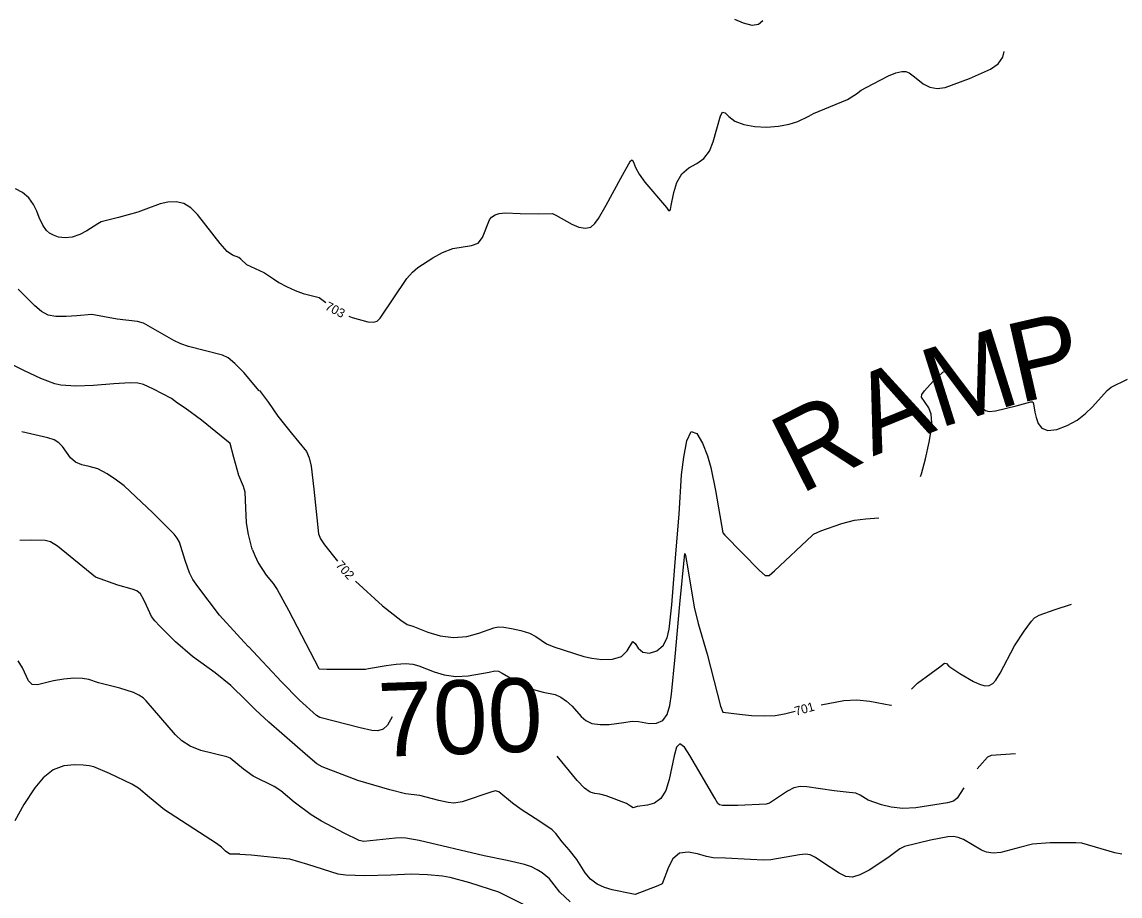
# Model space of a CAD drawing. Extents: x -291892836 to 2945206, y -477993085 to 1832792.
# Drawn here: x 1850526.8 to 1851017.9, y 544137.8 to 544528.7 of the extents above; entities that cross this region are included whole.
import ezdxf

# ---------------------------------------------------------------- set-up
doc = ezdxf.new("R2010")
doc.units = 0
for name, color, linetype in [('DT_X_Contour_Minor', 7, 'Continuous'), ('DT_X_Terrain_Ground_Line', 7, 'Continuous'), ('Level 19', 7, 'Continuous'), ('Level 40', 7, 'Continuous')]:
    doc.layers.add(name, color=color, linetype=linetype)

msp = doc.modelspace()

# ---------------------------------------------------------------- linework, layer by layer
at = {"layer": 'DT_X_Contour_Minor'}
for points in [[(1850858.2, 544529.18), (1850856.23, 544527.62), (1850853.41, 544527.18), (1850849.6, 544528.12), (1850845.59, 544529.87)], [(1850673.08, 544397.16), (1850674.59, 544396.56), (1850681.6, 544394.53), (1850683.91, 544394.4), (1850685.65, 544394.96), (1850687.06, 544396.28), (1850699.04, 544413.96), (1850701.49, 544416.74), (1850703.86, 544418.83), (1850710.55, 544423.28), (1850714.99, 544425.67), (1850719.61, 544427.42), (1850727.86, 544428.69), (1850730.87, 544429.83), (1850732.86, 544432.27), (1850735.9, 544440.23), (1850736.79, 544441.36), (1850738.49, 544442.45), (1850740.22, 544443.02), (1850743.02, 544443.31), (1850749.6, 544443.09), (1850757.91, 544442.82), (1850764.05, 544442.99), (1850765.59, 544442.32), (1850772.75, 544438.2), (1850775.95, 544436.94), (1850778.89, 544436.42), (1850781.21, 544436.98), (1850783.06, 544438.52), (1850784.7, 544440.81), (1850788.07, 544446.84), (1850794.67, 544458.87), (1850798.93, 544466.58), (1850799.68, 544467), (1850800.32, 544465.95), (1850801.21, 544463.68), (1850802.82, 544460.58), (1850805.42, 544457.09), (1850815.08, 544445.74), (1850816.03, 544444.45), (1850816.59, 544444.45), (1850816.95, 544444.81), (1850817.24, 544446.56), (1850818.4, 544452.47), (1850819.76, 544456.9), (1850821.97, 544460.82), (1850825.11, 544463.43), (1850828.63, 544465.36), (1850831.86, 544467.62), (1850834.26, 544470.96), (1850835.94, 544475.09), (1850839.18, 544486.75), (1850840.16, 544488.35), (1850841.31, 544488.01), (1850843.01, 544486.38), (1850845.7, 544484.4), (1850849.67, 544482.84), (1850854.56, 544481.9), (1850859.89, 544481.65), (1850865.16, 544482.09), (1850869.95, 544483.03), (1850873.86, 544484.22), (1850878.78, 544486.63), (1850880.88, 544487.73), (1850896.06, 544494.02), (1850900.14, 544496.6), (1850902.15, 544498.21), (1850907.55, 544500.96), (1850914.35, 544504.56), (1850917.67, 544505.99), (1850920.27, 544506.61), (1850922.19, 544506.52), (1850923.63, 544505.98), (1850925.97, 544504.11), (1850929.9, 544501.05), (1850932.81, 544499.59), (1850936.16, 544498.92), (1850939.7, 544499.41), (1850950.67, 544503.35), (1850960.06, 544507.6), (1850963.42, 544510), (1850965.48, 544513.01), (1850966.07, 544515.42)], [(1850635.22, 544416.57), (1850627.45, 544420.14), (1850624.75, 544422.58), (1850623.83, 544423.36), (1850621.01, 544424.35), (1850618.67, 544426.12), (1850615.56, 544429.59), (1850605.39, 544442.67), (1850602.41, 544445.64), (1850599.29, 544447.54), (1850595.79, 544448.31), (1850592.12, 544448.17), (1850588.61, 544447.43), (1850582.28, 544445.05), (1850578.69, 544443.71), (1850570.04, 544441.32), (1850562.34, 544439.25), (1850560.81, 544438.49), (1850555.84, 544435.36), (1850552.67, 544433.72), (1850549.29, 544432.53), (1850546.1, 544432.17), (1850543.26, 544432.52), (1850540.92, 544433.32), (1850539.15, 544434.31), (1850537.85, 544435.41), (1850536.11, 544437.76), (1850534.57, 544441.27), (1850533.5, 544444.03), (1850532, 544447.14), (1850529.88, 544450.09), (1850527.07, 544452.45), (1850523.97, 544454.04)], [(1850635.22, 544416.57), (1850635.37, 544416.5), (1850639.33, 544413.85), (1850641.76, 544412.23), (1850645.15, 544410.37), (1850649.02, 544408.57), (1850652.68, 544407.23), (1850659.82, 544405.53), (1850662.72, 544403.25)], [(1850633, 544363.79), (1850626.07, 544371.88), (1850622.02, 544376.03), (1850619, 544378.48), (1850616.49, 544379.69), (1850601.32, 544383.53), (1850597.87, 544384.83), (1850594.82, 544386.32), (1850581.2, 544394.02), (1850578.51, 544394.8), (1850569.39, 544395.84), (1850558.08, 544397.89), (1850551.41, 544397.35), (1850546.57, 544396.97), (1850542.02, 544396.97), (1850538.51, 544397.65), (1850535.61, 544399.21), (1850532.59, 544401.81), (1850525.13, 544409.15)], [(1850630.02, 544292.56), (1850629.68, 544293.46), (1850628.11, 544299.5), (1850627.21, 544304.78), (1850626.98, 544311.41), (1850626.66, 544318.44), (1850625.99, 544320.91), (1850623.83, 544325.93), (1850621.53, 544333.92), (1850619.91, 544340.21), (1850607.15, 544350.55), (1850599.88, 544355.97), (1850596.44, 544358.22), (1850593.68, 544360.32), (1850585.7, 544364.5), (1850581.23, 544366.63), (1850578.63, 544367.2), (1850575.29, 544367.37), (1850567.98, 544366.94), (1850558.79, 544366.08), (1850550.87, 544365.88), (1850544.2, 544366.29), (1850541.61, 544366.87), (1850535.31, 544369.3), (1850527.94, 544372.75), (1850522.57, 544375.36)], [(1850928.73, 544325.47), (1850929.1, 544326.61), (1850930.94, 544333.27), (1850932.57, 544340.8), (1850933.31, 544345.16), (1850933.71, 544349.5), (1850933.46, 544353.29), (1850932.39, 544356.12), (1850929.1, 544360.87), (1850929.36, 544362.15), (1850930.44, 544363.75), (1850934.38, 544368.01), (1850938.62, 544372.04), (1850939.43, 544372.4), (1850940.38, 544372.28), (1850941.41, 544371.45), (1850944.11, 544368.51), (1850949.77, 544363.87), (1850952.35, 544360.63), (1850954.52, 544357.82), (1850956.73, 544355.74), (1850957.8, 544354.97), (1850959.41, 544354.57), (1850962.24, 544354.79), (1850971.52, 544357.06), (1850977.99, 544358.84), (1850978.94, 544358.77), (1850979.22, 544357.95), (1850979.84, 544354.24), (1850980.44, 544351.74), (1850981.38, 544349.17), (1850983, 544347.06), (1850985.68, 544346.02), (1850989.6, 544346.48), (1850994.21, 544348.18), (1850998.72, 544350.68), (1851002.54, 544353.56), (1851005.65, 544356.56), (1851012.12, 544363.9), (1851013.94, 544365.35), (1851021.3, 544368.95)], [(1850633.01, 544363.87), (1850637.17, 544358.46), (1850641.34, 544352.42), (1850647.29, 544344.96), (1850654.11, 544336.65), (1850655.29, 544333.83), (1850656.15, 544330.01), (1850657.42, 544319.78), (1850659.41, 544299.78), (1850660.31, 544297.62), (1850662.14, 544294.93), (1850667.97, 544287.54)], [(1850628.2, 544249.3), (1850626.24, 544251.4), (1850615.19, 544263.38), (1850605.44, 544276.19), (1850603.3, 544279.43), (1850601.8, 544282.37), (1850599.9, 544287.92), (1850597.23, 544296.05), (1850596.28, 544297.85), (1850594.9, 544299.59), (1850585.39, 544309.12), (1850572.49, 544321.26), (1850569.1, 544323.86), (1850564.98, 544326.61), (1850560.75, 544328.79), (1850556.93, 544329.97), (1850553.62, 544330.69), (1850550.86, 544331.79), (1850548.61, 544333.82), (1850545.04, 544338.79), (1850543.31, 544340.55), (1850541.2, 544341.77), (1850538.37, 544342.69), (1850526.77, 544345.46)], [(1850675.98, 544278.61), (1850688.07, 544267.63), (1850696.36, 544261.13), (1850699.06, 544259.3), (1850701.72, 544258.54), (1850708.38, 544255.84), (1850713.83, 544254.19), (1850719.87, 544253.37), (1850725.84, 544253.94), (1850731.17, 544255.37), (1850737.92, 544257.82), (1850739.89, 544258.15), (1850742.28, 544257.99), (1850745.85, 544257.45), (1850750.02, 544256.55), (1850753.83, 544255.32), (1850756.65, 544253.83), (1850761.48, 544250.65), (1850764.77, 544249.28), (1850778.19, 544244.97), (1850781.75, 544244.16), (1850786.23, 544243.62), (1850790.94, 544243.74), (1850794.94, 544244.99), (1850797.54, 544247.5), (1850800.05, 544251.58), (1850801.03, 544250.75), (1850802.39, 544248.68), (1850804.49, 544246.84), (1850807.49, 544246.43), (1850810.8, 544247.51), (1850813.64, 544249.88), (1850815.43, 544253.27), (1850816.36, 544257.16), (1850817.45, 544267.97), (1850819.3, 544290.85), (1850820.75, 544308.65), (1850821.84, 544326.11), (1850822.78, 544334.07), (1850824.21, 544341.36), (1850826.15, 544345.48), (1850828.59, 544344.7), (1850831.14, 544340.39), (1850833.36, 544334.74), (1850834.93, 544329.45), (1850836.94, 544319.22), (1850840.23, 544300.25), (1850841.25, 544299.12), (1850856.75, 544283.37), (1850859.23, 544281.18), (1850860.99, 544281.16), (1850863.47, 544283.22), (1850880.23, 544299.04), (1850880.82, 544299.68), (1850884.14, 544301.11), (1850893.54, 544304.44), (1850899.11, 544305.86), (1850904.23, 544306.55), (1850910.02, 544306.9)], [(1850627.19, 544225.32), (1850620.28, 544231.99), (1850613.19, 544237.62), (1850603.08, 544244.91), (1850595.48, 544251.52), (1850588.48, 544258.45), (1850586.29, 544260.86), (1850584.83, 544262.85), (1850582.51, 544267.74), (1850581.22, 544270.6), (1850579.81, 544272.94), (1850578.21, 544274.3), (1850576.17, 544275.05), (1850569.69, 544276.85), (1850559.75, 544280.35), (1850542.7, 544294.29), (1850539.58, 544296.14), (1850537.17, 544296.76), (1850530.47, 544296.94), (1850525.92, 544296.78)], [(1850630.02, 544292.56), (1850630.92, 544290.17), (1850632.54, 544286.85), (1850636.11, 544281.27), (1850639.12, 544277.55), (1850640.93, 544274.89), (1850646, 544265.66), (1850659.55, 544239.57), (1850659.81, 544239.43), (1850663.12, 544239.23), (1850680.51, 544239.28), (1850681.8, 544239.63), (1850689.69, 544240.96), (1850694.13, 544241.53), (1850698.3, 544241.79), (1850701.59, 544241.51), (1850704.41, 544240.72), (1850711.17, 544238.05), (1850715.67, 544236.73), (1850720.81, 544236.04), (1850726.37, 544236.29), (1850735.8, 544237.99), (1850738.33, 544238.45), (1850739.95, 544238.32), (1850741.66, 544237.48), (1850750.84, 544232.09), (1850754.05, 544230.69), (1850759.87, 544229.05), (1850765.27, 544227.88), (1850767.88, 544226.76), (1850770.43, 544224.96), (1850772.84, 544222.69), (1850776.92, 544218.09), (1850779, 544216.27), (1850781.72, 544215.04), (1850785.39, 544214.53), (1850789.46, 544214.57), (1850796.05, 544215.37), (1850799.67, 544216.02), (1850802.55, 544215.81), (1850807.51, 544215), (1850810.67, 544215.07), (1850813.47, 544216.24), (1850815.39, 544218.95), (1850816.58, 544223.01), (1850817.35, 544228.03), (1850818.93, 544244.76), (1850821.1, 544268.33), (1850823.24, 544291.06), (1850823.59, 544290.15), (1850824.63, 544284.2), (1850827.48, 544267.01), (1850829.23, 544259.67), (1850833.26, 544246.04), (1850839.32, 544222.77), (1850840.24, 544220.01), (1850847.75, 544219.1), (1850853.16, 544218.61), (1850858.73, 544218.38), (1850863.64, 544218.62), (1850867.83, 544219.24), (1850872.59, 544220.43)], [(1850924.73, 544230.33), (1850927.38, 544232.96), (1850933.48, 544237.51), (1850937.4, 544240.25), (1850939.47, 544241.94), (1850940.27, 544241.74), (1850941.43, 544240.58), (1850946.3, 544237.4), (1850952.4, 544233.79), (1850955.15, 544232.51), (1850957.49, 544231.87), (1850959.46, 544231.99), (1850961.08, 544232.9), (1850962.38, 544234.34), (1850964.28, 544237.44), (1850970.79, 544249.76), (1850975.03, 544256.2), (1850978.3, 544260.76), (1850979.74, 544262.19), (1850981.79, 544263.38), (1850988.45, 544265.74), (1850996.26, 544268.34)], [(1850692.36, 544217.89), (1850690.27, 544214.24), (1850688.42, 544212.46), (1850686, 544211.76), (1850683.27, 544211.88), (1850678.15, 544212.99), (1850660.13, 544217.62), (1850658.5, 544218.56), (1850651.02, 544225.45), (1850642.94, 544233.53), (1850628.2, 544249.39)], [(1850625.91, 544194.6), (1850619.99, 544199.43), (1850618.46, 544200.06), (1850606.8, 544202.92), (1850602.01, 544204.82), (1850598.29, 544207.24), (1850595.5, 544209.96), (1850582.44, 544225.12), (1850581, 544226.41), (1850579.13, 544227.66), (1850576.74, 544228.82), (1850570.68, 544230.8), (1850561.15, 544233.08), (1850556.7, 544234.67), (1850553.91, 544235.15), (1850550.03, 544235.2), (1850545.51, 544234.82), (1850540.98, 544234.04), (1850533.78, 544232.23), (1850531.37, 544232.44), (1850529.75, 544234.05), (1850527.11, 544239.89), (1850525.14, 544242.97)], [(1851018.72, 544156.5), (1851015.55, 544157.12), (1851000.88, 544161.38), (1850998.13, 544161.63), (1850986.66, 544161.55), (1850978.75, 544160.99), (1850973.51, 544159.72), (1850964.61, 544157.32), (1850961.18, 544156.99), (1850958.18, 544157.4), (1850955.97, 544158.37), (1850947.94, 544163.04), (1850945.55, 544164.02), (1850943.39, 544164.44), (1850940.98, 544164.32), (1850933.1, 544162.73), (1850921.57, 544159.97), (1850919.52, 544158.94), (1850914.05, 544154.82), (1850905.76, 544149.39), (1850901.59, 544147.24), (1850898.26, 544146.3), (1850895.37, 544146.59), (1850892.33, 544147.99), (1850884.97, 544152.83), (1850881.73, 544154.99), (1850879.39, 544156.21), (1850877.31, 544156.56), (1850874.6, 544156.26), (1850861.83, 544154.05), (1850858.52, 544153.79), (1850852.72, 544154.08), (1850841.45, 544154.67), (1850835.96, 544154.92), (1850832.93, 544155.55), (1850829.01, 544156.68), (1850824.74, 544157.49), (1850820.86, 544156.94), (1850817.96, 544154.38), (1850816.01, 544150.74), (1850813.14, 544143.21), (1850811.16, 544142.33), (1850801.07, 544138.5), (1850799.62, 544138.75), (1850790.78, 544140.51), (1850787.42, 544141.6), (1850784.07, 544143.17), (1850781.09, 544145.35), (1850778.73, 544148.19), (1850775.07, 544154.19), (1850771.51, 544158.45), (1850768.48, 544162.11), (1850765.68, 544165.79), (1850763.9, 544167.4), (1850758.41, 544171.09), (1850750.04, 544176.53), (1850746.21, 544179.3), (1850740.04, 544184.48), (1850738.6, 544184.79), (1850736.94, 544184.46), (1850723.72, 544179.92), (1850719.99, 544179.34), (1850717.42, 544179.64), (1850713.32, 544180.5), (1850704.77, 544182.83), (1850698.39, 544183.45), (1850691.42, 544185.26), (1850677.11, 544189.52), (1850661.15, 544195.53), (1850658.75, 544196.98), (1850654.66, 544200.38), (1850637.22, 544215.59), (1850631.28, 544221.05), (1850627.19, 544225.32)], [(1850884.24, 544223.33), (1850894.44, 544225.22), (1850900.18, 544225.48), (1850906, 544224.89), (1850915.43, 544223.13), (1850915.76, 544223.13)], [(1850948.1, 544186.26), (1850945.03, 544181.51), (1850943.42, 544180.24), (1850940.72, 544179.44), (1850926.53, 544177.23), (1850920.86, 544177.01), (1850915.64, 544177.52), (1850911.19, 544178.53), (1850905.3, 544180.71), (1850901.65, 544182.95), (1850899.74, 544183.84), (1850896.74, 544184.16), (1850890.13, 544184.9), (1850877.85, 544186.69), (1850874.87, 544186.78), (1850872.09, 544186.17), (1850869.26, 544184.71), (1850861.2, 544179.3), (1850859.62, 544178.89), (1850847.02, 544178.35), (1850840.19, 544178.31), (1850838.82, 544178.61), (1850838.11, 544179.17), (1850836.67, 544181.55), (1850825.55, 544200.73), (1850823.12, 544204.43), (1850821.1, 544205.92), (1850819.6, 544204.37), (1850818.46, 544200.49), (1850816.29, 544189.94), (1850814.77, 544185.06), (1850812.61, 544181.37), (1850809.71, 544179.35), (1850806.56, 544178.52), (1850801.97, 544177.8), (1850800.16, 544177.27), (1850799.03, 544178.01), (1850797.27, 544179.13), (1850788.05, 544182.58), (1850785.3, 544183.32), (1850783.09, 544183.66), (1850781.01, 544184.26), (1850778.49, 544186.02), (1850775.16, 544189.5), (1850766.19, 544200.3)], [(1850971.22, 544201.39), (1850960.27, 544200.6), (1850958.71, 544199.88), (1850955.18, 544196.09), (1850954.1, 544194.67)], [(1850624.31, 544156.51), (1850619.81, 544156.55), (1850617.89, 544157.83), (1850616.1, 544159.62), (1850613.88, 544161.25), (1850590.65, 544176.38), (1850583.93, 544181.85), (1850578.99, 544186), (1850575.96, 544187.82), (1850565.97, 544192.59), (1850558.95, 544195.57), (1850556.97, 544196.02), (1850554.23, 544196.34), (1850550.3, 544196.52), (1850545.59, 544196.03), (1850540.74, 544194.2), (1850536.3, 544190.65), (1850532.54, 544186.2), (1850527.71, 544178.68), (1850523.61, 544171.4)], [(1850772.05, 544135.19), (1850767.39, 544139.51), (1850764.93, 544142.87), (1850762.78, 544145.57), (1850759.46, 544148.15), (1850757.28, 544149.51), (1850754.68, 544150.83), (1850751.61, 544151.97), (1850743.79, 544153.69), (1850733.53, 544155.81), (1850704.52, 544162.6), (1850698.45, 544163.69), (1850696.59, 544163.8), (1850693.83, 544163.67), (1850679.7, 544162.13), (1850677.63, 544162.64), (1850670.92, 544165.86), (1850660.88, 544171.28), (1850656.24, 544174.18), (1850648.57, 544179.82), (1850642.56, 544184.85), (1850639.7, 544186.82), (1850630.23, 544191.47), (1850625.91, 544194.61)], [(1850624.31, 544156.51), (1850629.29, 544156.17), (1850646.5, 544154.38), (1850654.58, 544152.05), (1850668.12, 544147.68), (1850671.73, 544147.25), (1850679.98, 544147.02), (1850691.8, 544147.35), (1850700.9, 544147.76), (1850708.23, 544147.5), (1850714.94, 544146.86), (1850718.14, 544146.27), (1850726.97, 544143.88), (1850739.94, 544139.72), (1850752.19, 544133.57)]]:
    msp.add_lwpolyline(points, dxfattribs=at)

# ---------------------------------------------------------------- texts
at = {"layer": 'DT_X_Terrain_Ground_Line'}
msp.add_text('700', height=33, rotation=2.034, dxfattribs=at).set_placement((1850686.63, 544200.01))
at = {"layer": 'Level 19'}
for s, rotation, p in [('703', 332.5562, (1850662.06, 544400.31)), ('702', 312.0443, (1850666.93, 544285.56)), ('701', 15.7621, (1850873.01, 544218.41))]:
    msp.add_text(s, height=4, rotation=rotation, dxfattribs=at).set_placement(p)
at = {"layer": 'Level 40'}
for s, rotation, p in [('P', 12.8736, (1850972.69, 544358.12)), ('M', 17.5049, (1850936.82, 544346.88)), ('A', 22.1361, (1850907.35, 544334.33)), ('R', 26.7674, (1850874.81, 544317.18))]:
    msp.add_text(s, height=35.5, rotation=rotation, dxfattribs=at).set_placement(p)

doc.saveas('drawing.dxf')
